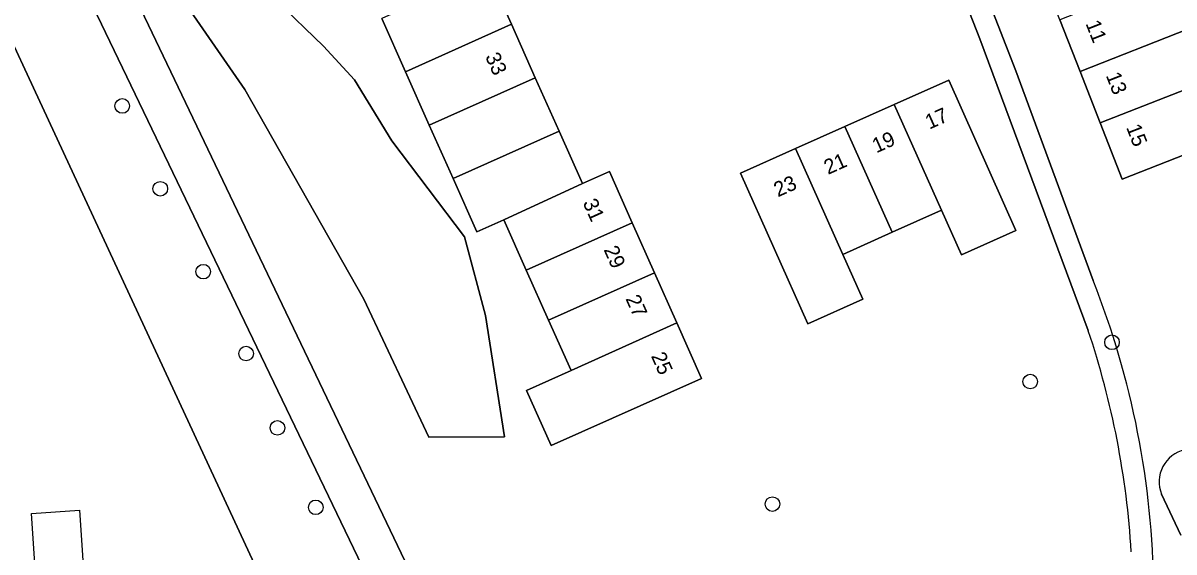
# Model space of a CAD drawing. Extents: x 159451 to 160664, y 388402 to 389723.
# Drawn here: x 159509 to 159586.1, y 389193.6 to 389229 of the extents above; entities that cross this region are included whole.
import ezdxf

# ---------------------------------------------------------------- set-up
doc = ezdxf.new("R2010")
doc.units = 0
for name, color, linetype in [('IMGEO_Boom', 7, 'Continuous'), ('IMGEO_Bouwland', 7, 'Continuous'), ('IMGEO_Grasland_overig', 7, 'Continuous'), ('IMGEO_Groenvoorziening', 7, 'Continuous'), ('IMGEO_Meer_plas_ven_vijver', 7, 'Continuous'), ('IMGEO_Pand', 7, 'Continuous'), ('IMGEO_Pand_nummerreeks', 7, 'Continuous'), ('IMGEO_Pand_vergunning_verleend', 7, 'Continuous'), ('IMGEO_Rijbaan_lokaal_gesloten', 7, 'Continuous')]:
    doc.layers.add(name, color=color, linetype=linetype)

msp = doc.modelspace()

# ---------------------------------------------------------------- linework, layer by layer
at = {"layer": 'IMGEO_Boom'}
for centre in [(159515.645, 389223.44), (159518.196, 389217.898), (159521.076, 389212.352), (159581.959, 389207.626), (159523.945, 389206.87), (159576.482, 389204.996), (159526.044, 389201.9), (159528.616, 389196.58), (159559.207, 389196.795)]:
    msp.add_circle(centre, 0.489, dxfattribs=at)
at = {"layer": 'IMGEO_Bouwland'}
for points in [[(159521.25, 389297.74), (159493.172, 389293.777), (159486.712, 389292.863), (159536.847, 389188.304)], [(159565.813, 389253.186), (159564.916, 389253.004), (159575.523, 389225.793), (159580.698, 389211.752)], [(159580.373, 389208.403), (159573.107, 389227.927), (159563.374, 389252.707), (159559.597, 389251.864), (159562.085, 389239.938), (159557.562, 389237.923), (159558.351, 389236.161), (159554.447, 389234.413), (159550.543, 389232.664), (159545.842, 389243.23), (159548.614, 389244.465), (159547.283, 389247.447), (159522.997, 389237.416), (159523.334, 389236.494), (159515.988, 389233.475), (159514.682, 389236.714), (159522.027, 389239.718), (159536.816, 389245.805), (159535.285, 389249.699)], [(159540.13, 389232.476), (159541.724, 389228.904), (159543.319, 389225.331), (159544.914, 389221.759), (159546.482, 389218.246), (159548.293, 389219.053), (159549.821, 389215.625), (159551.319, 389212.262), (159552.806, 389208.926), (159554.466, 389205.201), (159544.38, 389200.71), (159542.733, 389204.393), (159545.715, 389205.735), (159544.217, 389209.098), (159542.719, 389212.462), (159541.221, 389215.825), (159539.413, 389215.017), (159537.817, 389218.589), (159536.221, 389222.16), (159534.626, 389225.732), (159533.03, 389229.303)], [(159586.574, 389194.724), (159585.284, 389197.461)]]:
    msp.add_lwpolyline(points, dxfattribs=at)
for points in [[(159487.441, 389272.575), (159480.836, 389288.81), (159478.228, 389288.738), (159479.211, 389271.897), (159488.551, 389179.124), (159490.78, 389160.929), (159492.959, 389147.253), (159495.943, 389125.547), (159496.063, 389124.735), (159496.335, 389123.276), (159496.729, 389122.189), (159497.183, 389121.597), (159498.11, 389121.139), (159499.541, 389121.106), (159518.516, 389121.775), (159539.156, 389122.203), (159538.081, 389141.023), (159537.243, 389155.693), (159534.303, 389168.702), (159530.224, 389180.456)], [(159585.725, 389232.05), (159587.076, 389228.593), (159588.427, 389225.136), (159591.484, 389226.33), (159592.944, 389222.587), (159582.637, 389218.552), (159581.17, 389222.301), (159579.818, 389225.756), (159578.465, 389229.213), (159577.145, 389232.586), (159574.908, 389231.714), (159573.541, 389235.222), (159572.208, 389238.644), (159570.876, 389242.061), (159569.411, 389245.821), (159579.696, 389249.831), (159581.176, 389246.078), (159578.122, 389244.887), (159579.454, 389241.465), (159580.787, 389238.042), (159582.119, 389234.62), (159584.374, 389235.507)], [(159525.975, 389230.482), (159529.13, 389227.44), (159531.217, 389225.185), (159533.719, 389221.109), (159538.578, 389214.693), (159539.985, 389209.42), (159541.252, 389201.297), (159536.188, 389201.27), (159531.83, 389210.522), (159523.869, 389224.551), (159518.626, 389232.107), (159523.847, 389234.341)], [(159575.526, 389215.111), (159571.872, 389213.475), (159570.533, 389216.466), (159567.228, 389214.986), (159563.922, 389213.506), (159565.263, 389210.512), (159561.582, 389208.865), (159557.07, 389218.943), (159560.751, 389220.586), (159564.059, 389222.063), (159567.367, 389223.539), (159571.032, 389225.175)]]:
    msp.add_lwpolyline(points, close=True, dxfattribs=at)
for centre, radius, start, end in [((159526.948, 389190.449), 57.817, 0.63291, 21.61987), ((159525.683, 389190.082), 57.677, 3.49045, 18.52015), ((159587.317, 389198.287), 2.194, 102.79301, 202.11589)]:
    msp.add_arc(centre, radius, start, end, dxfattribs=at)
at = {"layer": 'IMGEO_Grasland_overig'}
for points in [[(159486.712, 389292.863), (159483.087, 389292.351), (159491.324, 389276.977), (159493.1, 389273.212), (159500, 389258.58), (159504.093, 389250), (159534.245, 389187.399), (159541.062, 389164.374)], [(159543.868, 389152.492), (159543.663, 389144.191), (159543.127, 389122.477), (159551.705, 389123.07), (159550.85, 389135.446), (159552.375, 389144.269), (159550.196, 389160.656), (159546.355, 389164.126), (159540.689, 389183.824), (159539.945, 389186.409), (159538.67, 389189.107), (159536.847, 389188.304), (159486.712, 389292.863)]]:
    msp.add_lwpolyline(points, dxfattribs=at)
at = {"layer": 'IMGEO_Groenvoorziening'}
msp.add_lwpolyline([(159541.062, 389164.374), (159534.245, 389187.399), (159504.093, 389250), (159500, 389258.58), (159493.1, 389273.212), (159487.441, 389272.575), (159530.224, 389180.456), (159534.303, 389168.702), (159537.243, 389155.693), (159538.081, 389141.023), (159539.156, 389122.203), (159543.127, 389122.477), (159543.663, 389144.191)], dxfattribs=at)
at = {"layer": 'IMGEO_Meer_plas_ven_vijver'}
msp.add_lwpolyline([(159523.847, 389234.341), (159518.626, 389232.107), (159523.869, 389224.551), (159531.83, 389210.522), (159536.188, 389201.27), (159541.252, 389201.297), (159539.985, 389209.42), (159538.578, 389214.693), (159533.719, 389221.109), (159531.217, 389225.185), (159529.13, 389227.44), (159525.975, 389230.482)], close=True, dxfattribs=at)
msp.add_lwpolyline([(159585.284, 389197.461), (159586.574, 389194.724)], dxfattribs=at)
msp.add_arc((159587.317, 389198.287), 2.194, 102.79301, 202.11589, dxfattribs=at)
at = {"layer": 'IMGEO_Pand'}
for points in [[(159540.13, 389232.476), (159533.03, 389229.303), (159534.626, 389225.732), (159541.724, 389228.904)], [(159585.725, 389232.05), (159578.465, 389229.213), (159579.818, 389225.756), (159587.076, 389228.593)], [(159541.724, 389228.904), (159534.626, 389225.732), (159536.221, 389222.16), (159543.319, 389225.331)], [(159587.076, 389228.593), (159579.818, 389225.756), (159581.17, 389222.301), (159588.427, 389225.136)], [(159592.944, 389222.587), (159591.484, 389226.33), (159588.427, 389225.136), (159581.17, 389222.301), (159582.637, 389218.552)], [(159543.319, 389225.331), (159536.221, 389222.16), (159537.817, 389218.589), (159544.914, 389221.759)], [(159571.032, 389225.175), (159567.367, 389223.539), (159570.533, 389216.466), (159571.872, 389213.475), (159575.526, 389215.111)], [(159567.367, 389223.539), (159564.059, 389222.063), (159567.228, 389214.986), (159570.533, 389216.466)], [(159544.914, 389221.759), (159537.817, 389218.589), (159539.413, 389215.017), (159541.221, 389215.825), (159546.482, 389218.246)], [(159564.059, 389222.063), (159560.751, 389220.586), (159563.922, 389213.506), (159567.228, 389214.986)], [(159560.751, 389220.586), (159557.07, 389218.943), (159561.582, 389208.865), (159565.263, 389210.512), (159563.922, 389213.506)], [(159549.821, 389215.625), (159548.293, 389219.053), (159546.482, 389218.246), (159541.221, 389215.825), (159542.719, 389212.462)], [(159551.319, 389212.262), (159549.821, 389215.625), (159542.719, 389212.462), (159544.217, 389209.098)], [(159552.806, 389208.926), (159551.319, 389212.262), (159544.217, 389209.098), (159545.715, 389205.735)], [(159554.466, 389205.201), (159552.806, 389208.926), (159545.715, 389205.735), (159542.733, 389204.393), (159544.38, 389200.71)]]:
    msp.add_lwpolyline(points, close=True, dxfattribs=at)
at = {"layer": 'IMGEO_Pand_vergunning_verleend'}
msp.add_lwpolyline([(159509.568, 389196.173), (159512.785, 389196.387), (159513.592, 389184.311), (159510.374, 389184.096)], close=True, dxfattribs=at)
at = {"layer": 'IMGEO_Rijbaan_lokaal_gesloten'}
for points in [[(159580.698, 389211.752), (159575.523, 389225.793), (159564.916, 389253.004), (159565.813, 389253.186)], [(159559.597, 389251.864), (159563.374, 389252.707), (159573.107, 389227.927), (159580.373, 389208.403)]]:
    msp.add_lwpolyline(points, dxfattribs=at)
for centre, radius, start, end in [((159526.948, 389190.449), 57.817, 0.63291, 21.61987), ((159525.683, 389190.082), 57.677, 3.49045, 18.52015)]:
    msp.add_arc(centre, radius, start, end, dxfattribs=at)

# ---------------------------------------------------------------- texts
at = {"layer": 'IMGEO_Pand_nummerreeks'}
for s, rotation, p in [('11', 291.37112, (159580.175, 389228.96)), ('33', 294.05829, (159539.946, 389226.755)), ('13', 291.37112, (159581.534, 389225.488)), ('17', 24.05277, (159569.723, 389221.853)), ('15', 291.37112, (159582.895, 389222.01)), ('19', 24.05277, (159566.172, 389220.268)), ('21', 24.05277, (159562.937, 389218.824)), ('23', 24.05277, (159559.575, 389217.323)), ('31', 294.01818, (159546.484, 389216.971)), ('29', 294.01818, (159547.886, 389213.825)), ('27', 294.01818, (159549.35, 389210.54)), ('25', 294.01818, (159551.058, 389206.707))]:
    msp.add_text(s, height=1, rotation=rotation, dxfattribs=at).set_placement(p)

doc.saveas('drawing.dxf')
